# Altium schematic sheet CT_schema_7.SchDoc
size 287 x 160 mm
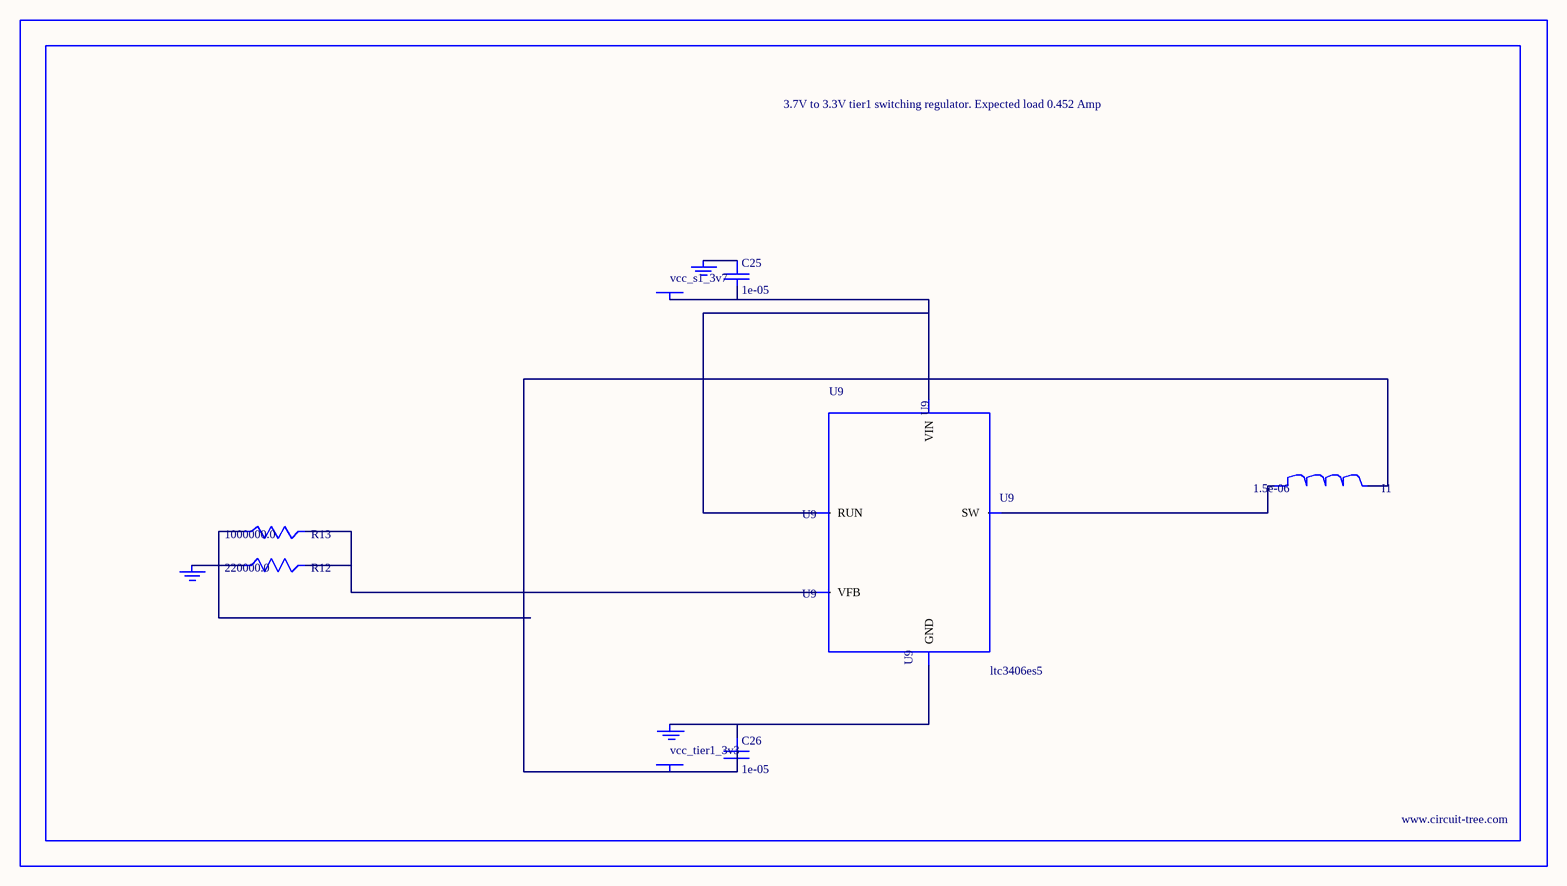
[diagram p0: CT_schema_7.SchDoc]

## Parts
BORDER6  (no value)
C25  1e-05  [C0805]
C26  1e-05  [C0805]
GND_INSTANCE_6_0  (no value)
GND_INSTANCE_6_1  (no value)
GND_INSTANCE_6_2  (no value)
I1  1.5e-06  [L0806]
POWER_INSTANCE_6_0  vcc_tier1_3v3
POWER_INSTANCE_6_1  vcc_s1_3v7
R12  220000.0  [R0603]
R13  1000000.0  [R0603]
U9  ltc3406es5  [TSOT-23-5]

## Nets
NetC25_1: C25.1 GND_INSTANCE_6_1.0(GND)
NetC25_2: C25.2 POWER_INSTANCE_6_1.0(PWR) U9.1(RUN) U9.4(VIN)
NetC26_1: C26.1 GND_INSTANCE_6_0.0(GND) U9.2(GND)
NetC26_2: C26.2 I1.2 POWER_INSTANCE_6_0.0(PWR) R13.1
NetGND_INSTANCE_6_2_0: GND_INSTANCE_6_2.0(GND) R12.1
NetI1_1: I1.1 U9.3(SW)
NetR12_2: R12.2 R13.2 U9.5(VFB)

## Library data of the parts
BORDER6 = BORDER_PAGE6
C25 C26 = C0805C106K8RACTU
GND_INSTANCE_6_0-GND_INSTANCE_6_2 = GND
I1 = L0806C1R5MDWIT
POWER_INSTANCE_6_0 POWER_INSTANCE_6_1 = PWR
R12 = RC0603JR-07220KL
R13 = RC0603JR-071ML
